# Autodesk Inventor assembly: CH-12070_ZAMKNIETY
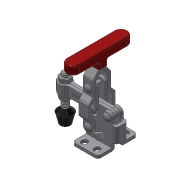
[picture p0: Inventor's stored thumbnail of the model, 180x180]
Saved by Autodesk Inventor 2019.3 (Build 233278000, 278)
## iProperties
Company: Î¢ÈíÖÐ¹ú
Created: 2015-08
Part Number: CH-12070_ZAMKNIETY
Material: Ogólny
Description: STEP AP203
Document SubType Name: Assembly
Designer: CADENGINEERING4
Sending System: SolidWorks 2012
Preprocessor: SwSTEP 2.0
Title: CH-12070.STEP
Author: Î¢ÈíÓÃ»§
Revision Number: ÈÎºÎ
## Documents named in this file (9)
- D:\Vault_2016\Projekty\NASZ KATALOG\CLAMPTEK\STRONA\Vertical toggle clamp\CH-12070\CH-12070_ZAMKNIETY.iam
- D:\Vault_2016\Projekty\NASZ KATALOG\CLAMPTEK\STEP FILES\Vertical toggle clamp\CH-12070\CH-12050-01 FLANGED BASE.ipt
- D:\Vault_2016\Projekty\NASZ KATALOG\CLAMPTEK\STEP FILES\Vertical toggle clamp\CH-12070\CH-12070-02 FIXED SPINDLE.ipt
- D:\Vault_2016\Projekty\NASZ KATALOG\CLAMPTEK\STEP FILES\Vertical toggle clamp\CH-12070\CH-12070-03 T-HANDLE.ipt
- D:\Vault_2016\Projekty\NASZ KATALOG\CLAMPTEK\STEP FILES\Vertical toggle clamp\CH-12070\CH-12050-07.ipt
- D:\Vault_2016\Projekty\NASZ KATALOG\CLAMPTEK\STEP FILES\Vertical toggle clamp\CH-12070\CH-12050-06.ipt
- D:\Vault_2016\Projekty\NASZ KATALOG\CLAMPTEK\STEP FILES\Vertical toggle clamp\CH-12070\CH-12050-04 CONNECTING-PLATE.ipt
- D:\Vault_2016\Projekty\NASZ KATALOG\CLAMPTEK\STEP FILES\Vertical toggle clamp\CH-12070\CH-FC-14134 Nut.ipt
- D:\Vault_2016\Projekty\NASZ KATALOG\CLAMPTEK\STEP FILES\Vertical toggle clamp\CH-12070\CH-FC-14134 SPINDLE SUPPLIED.ipt
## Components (11 placed, 11 different names)
1. CH-12050-01 FLANGED BASE_1
2. CH-12070-02 FIXED SPINDLE_2
3. CH-12070-03 T-HANDLE_3
4. CH-12050-07_4
5. CH-12050-07_5
6. CH-12050-06_6
7. CH-12050-04 CONNECTING-PLATE_7
8. CH-12050-06_8
9. CH-FC-14134 Nut_9
10. CH-FC-14134 SPINDLE SUPPLIED_10
11. CH-FC-14134 Nut_11
